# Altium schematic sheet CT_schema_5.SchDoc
size 293 x 156 mm
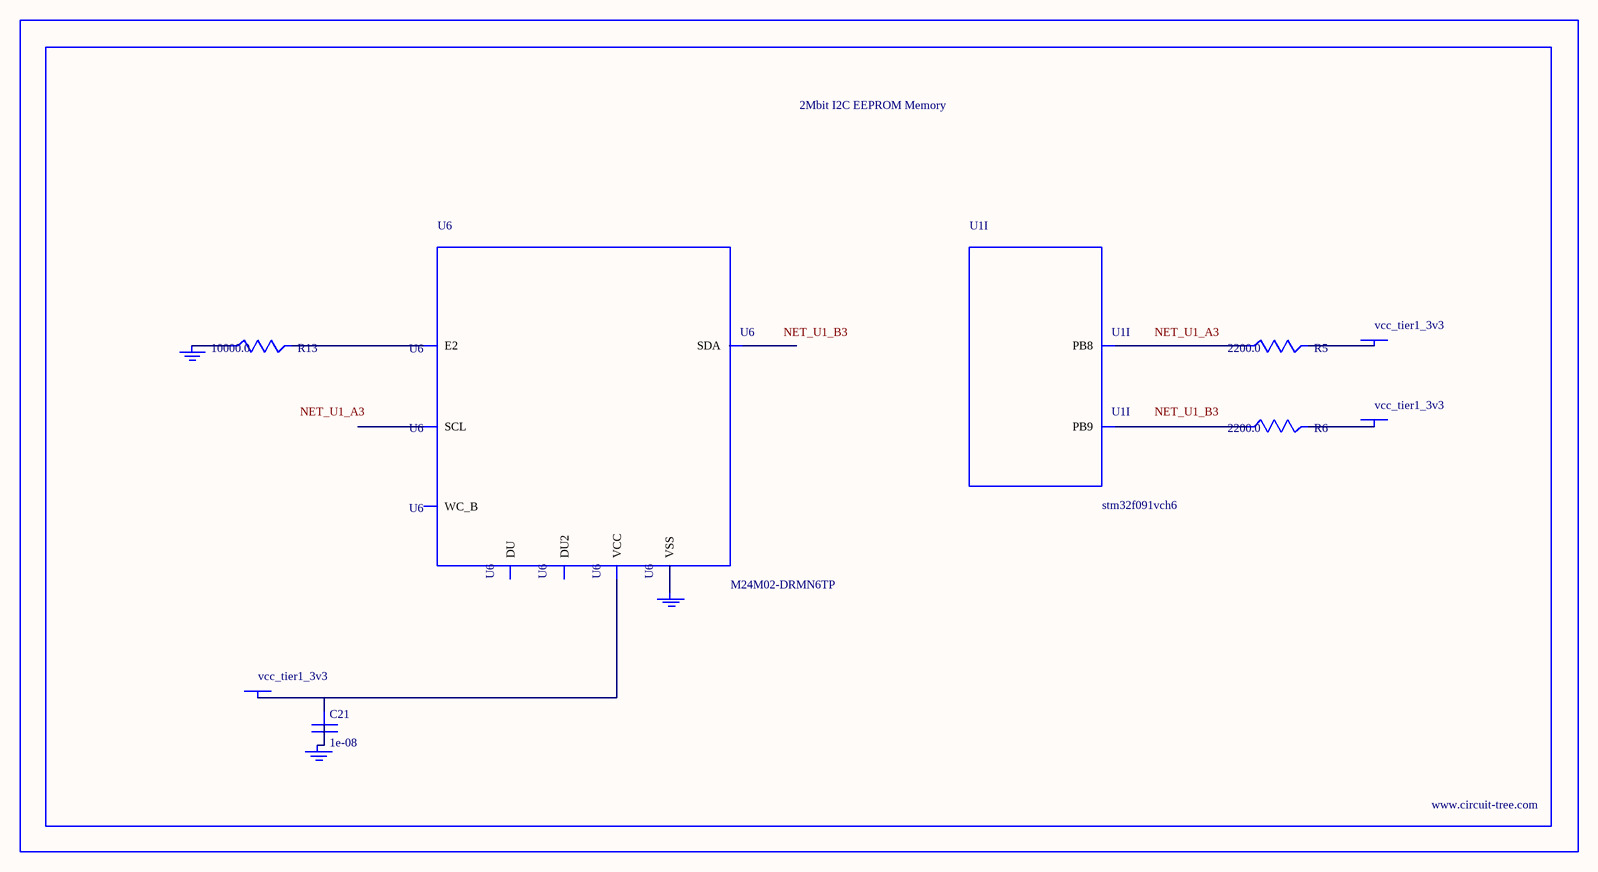
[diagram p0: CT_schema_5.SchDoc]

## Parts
BORDER4  (no value)
C21  1e-08  [C0402]
GND_INSTANCE_4_0  (no value)
GND_INSTANCE_4_1  (no value)
GND_INSTANCE_4_2  (no value)
POWER_INSTANCE_4_0  vcc_tier1_3v3
POWER_INSTANCE_4_1  vcc_tier1_3v3
POWER_INSTANCE_4_2  vcc_tier1_3v3
R5  2200.0  [R0603]
R6  2200.0  [R0603]
R13  10000.0  [R0603]
U1  stm32f091vch6  [UFBGA100]  (part I of 9)
U6  M24M02-DRMN6TP  [SOIC-8]

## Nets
NetC21_1: C21.1 POWER_INSTANCE_4_0.0(PWR) U6.8(VCC)
NetC21_2: C21.2 GND_INSTANCE_4_1.0(GND)
NetGND_INSTANCE_4_0_0: GND_INSTANCE_4_0.0(GND) R13.1
NetGND_INSTANCE_4_2_0: GND_INSTANCE_4_2.0(GND) U6.4(VSS)
NetPOWER_INSTANCE_4_1_0: POWER_INSTANCE_4_1.0(PWR) R5.2
NetPOWER_INSTANCE_4_2_0: POWER_INSTANCE_4_2.0(PWR) R6.2
NetR5_1: R5.1 U1.A3(PB8)
NetR6_1: R6.1 U1.B3(PB9)
NetR13_2: R13.2 U6.3(E2)

Not connected (* = marked no-connect by the designer): U6 1(DU) 2(DU2) 5(SDA) 6(SCL) 7(WC_B)

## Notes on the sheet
- Labels drawn without touching a wire or pin: NET_U1_A3, NET_U1_B3

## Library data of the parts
BORDER4 = BORDER_PAGE4
C21 = C0402C103K3RAC
GND_INSTANCE_4_0-GND_INSTANCE_4_2 = GND
POWER_INSTANCE_4_0-POWER_INSTANCE_4_2 = PWR
R5 R6 = RC0603JR-072K2L
R13 = RC0603JR-0710KL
